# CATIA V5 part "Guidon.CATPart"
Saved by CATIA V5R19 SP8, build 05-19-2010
Part number: Guidon
Nomenclature: 7
Material "Acier": density 7860 kg/m3, Young's modulus 2e+11 Pa, Poisson ratio 0.266, thermal expansion 1.17e-05 1/K
Bounding box of the stored display mesh (mm): x -362.5 to 362.5, y -92.642 to 482.568, z -19.996 to 296.41
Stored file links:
  C:\Users\rphgr\Desktop\0_Tapis_TC520B_vitesse\Guidon.CATPart
  D:\Documents\1_Travail\1 - ac-limoges.fr\ac-limoges.fr\Emmanuel Maynard - STI2D_Turgot\3 - Supports\Tapis de course TC520B\Tapis de course TC520B_Ca\0_Tapis_TC520B.CATProduct
  D:\Documents\1_Travail\1 - ac-limoges.fr\ac-limoges.fr\Emmanuel Maynard - STI2D_Turgot\3 - Supports\Tapis de course TC520B\Tapis de course TC520B_Ca\Montant_Gauche.CATPart
  D:\Programmes\DassaultSysteme\win_b64\startup\materials\French\Catalog.CATMaterial
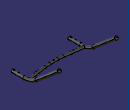
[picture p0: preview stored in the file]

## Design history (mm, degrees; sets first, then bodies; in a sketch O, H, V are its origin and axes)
Set1
  DatumPoint1
  DatumCurve1 to DatumCurve3
Body1 (main body)
  AxisSystem1: origin (0, 0, 0), X (1, 0, 0), Y (0, 1, 0), Z (0, 0, 1)
  Plane1: type OffsetPt, RefPlane YZ plane of AxisSystem1, RefPoint DatumPoint1
  Sketch1 on Plane1, origin (342.5, 0, 0), H (0, 1, 0), V (0, 0, 1)
    point P1 (-92.6422, 0)
    line L1 (-92.6422, 0) -> (47.3578, 0)
    arc A1 centre (47.3578, 240) radius 240 from (47.3578, 0) to (201.6268, 56.1493) ccw
    line L2 (201.6268, 56.1493) -> (469.7424, 281.125)
    reference projected line E1 through (-18.6422, 0) direction (0, -1) from edge of DatumCurve1
    distance E1 P1 = 74
    radius A1 = 240
    length L2 = 350
    angle L2 L1 = 140
    length L1 = 140
    coincidence: P1 H
    horizontal: L1 H
    tangency: A1 L1, L2 A1
  Plane2: type Normal, Curve Sketch1, RefPoint Sketch1.P1
  Plane3: type Angle, RefPlane XY plane of AxisSystem1, Direction edge [XY plane of AxisSystem1 | ZX plane of AxisSystem1], Angle 3
  Sketch2 on Plane2, origin (0, -92.6422, 0), H (-1, 0, 0), V (0, 0, 1)
    circle A1 centre (-342.5, 0) radius 20
    point P1 (-342.5, 0)
    reference projected point E1 (-342.5, 0) from Sketch1.L1
    circle A2 centre (-342.5, 0) radius 19
    radius A1 = 20
    distance A2 A1 = 1
    coincidence: P1 H, P1 E1
  Rib1: profile Sketch2, centre curve Sketch1
  Sketch3 on YZ plane of AxisSystem1, origin (0, 0, 0), H (0, 1, 0), V (0, 0, 1)
    circle A1 centre (57.1522, 2.9952) radius 16
    point P1 (57.1522, 2.9952)
    circle A2 centre (57.1522, 2.9952) radius 15
    reference projected point E1 (57.1522, 2.9952) from Sketch4.L1
    distance A2 A1 = 1
    radius A1 = 16
    coincidence: P1 E1
  Sketch4 on Plane3, origin (0, 0, 0), H (1, 0, 0), V (0, 0.9986, 0.0523)
    line L1 (0, 57.2307) -> (50, 57.2307)
    point P1 (0, 57.2307)
    line L2 (110.3332, 61.807) -> (342.5, 97.2307)
    point P2 (342.5, 97.2307)
    reference intersected line E1 through (0, -92.7693) direction (-1, 0) from face of Rib1
    arc A1 centre (50, 457.2307) radius 400 from (110.3332, 61.807) to (50, 57.2307) cw
    reference projected line E2 (342.5, 47.3578) -> (342.5, 201.6268) from Sketch1.A1
    distance P2 E1 = 190
    distance L1 P2 = 40
    radius A1 = 400
    length L1 = 50
    coincidence: P1 V, P2 E2
    horizontal: L1 H
    tangency: A1 L2, A1 L1
  Rib2: profile Sketch3, centre curve Sketch4
  Sketch5 on ZX plane of AxisSystem1, origin (0, 0, 0), H (0, 0, 1), V (1, 0, 0)
    construction line L1 (0, 71) -> (0, 50)
    point P1 (0, 71)
    point P2 (0, 50)
    line L2 (7.5, 71) -> (7.5, 50)
    line L3 (-7.5, 50) -> (-7.5, 71)
    arc A1 centre (0, 50) radius 7.5 from (7.5, 50) to (-7.5, 50) cw
    arc A2 centre (0, 71) radius 7.5 from (-7.5, 71) to (7.5, 71) cw
    reference intersected line E1 through (0, 0) direction (-1, 0) from YZ plane of AxisSystem1
    distance L1 L2 = 7.5
    length L1 = 21
    distance P2 E1 = 50
    coincidence: P1 V
    vertical: L1 V
    tangency: A1 L2, A2 L2, A1 L3, A2 L3
  Pocket1: profile Sketch5, direction (0, -1, 0), up to face of Rib2
  Sketch6 on XY plane of AxisSystem1, origin (0, 0, 0), H (1, 0, 0), V (0, 1, 0)
    circle A1 centre (0, 57.1522) radius 7.5
    point P1 (0, 57.1522)
    reference projected line E1 through (0, 57.1522) direction (1, 0) from axis of face of Rib2
    radius A1 = 7.5
    coincidence: P1 V, E1 P1
  Pocket2: profile Sketch6, direction (0, 0, 1), through (limit type 3)
  Line1: type PtDir, RefPoint {point type Center, Curve edge [face of Rib1 | face of Rib1]}, Direction face of Rib1, Start 0, End 20
  Point1: type Center, Curve edge [face of Rib2 | face of Rib2]
  Plane4: type 2Lines, Element1 {line type PtDir, RefPoint {point type Center, Curve edge [face of Rib2 | face of Rib2]}, Direction face of Rib2, Start 0, End 20}, Element2 Line1
  Sketch7 on Plane4, origin (-184.1754, 6.5265, -7.7779), H (-0.9891, -0.1469, -0.0047), V (-0.1151, 0.7541, 0.6466)
    construction line L1 (-419.3224, 15.4519) -> (-409.3225, 15.4024)
    point P1 (-419.3224, 15.4519)
    line L2 (-419.2927, 21.4518) -> (-409.2928, 21.4023)
    line L3 (-409.3522, 9.4024) -> (-419.3521, 9.4519)
    arc A1 centre (-409.3225, 15.4024) radius 6 from (-409.2928, 21.4023) to (-409.3522, 9.4024) cw
    arc A2 centre (-419.3224, 15.4519) radius 6 from (-419.3521, 9.4519) to (-419.2927, 21.4518) cw
    reference projected line E1 through (-179.4352, 14.2643) direction (-1, 0.005) from axis of face of Rib2
    reference intersected line E2 through (-534.4003, 0.0001) direction (-0.005, -1) from face of Rib2
    distance L1 L2 = 6
    length L1 = 10
    distance P1 E2 = 115
    tangency: A1 L2, A2 L2, A1 L3, A2 L3
    coincidence: L1 E1
  Pocket3: profile Sketch7, direction (0.0914, -0.6401, 0.7628), through (limit type 3)
  Sketch8 on Plane4, origin (-2.6366, 17.2415, -20.5476), H (0.9891, 0.1469, 0.0047), V (-0.1151, 0.7541, 0.6466)
    circle A1 centre (201.2414, 36.3328) radius 4
    point P1 (201.2414, 36.3328)
    circle A2 centre (265.2406, 36.6496) radius 4
    point P2 (265.2406, 36.6496)
    reference projected point E1 (228.241, 36.4665) from axis of face of Pocket3 from Sketch7.A1
    reference projected line E2 through (-0.0033, 35.3366) direction (1, 0.005) from axis of face of Rib2
    reference projected line E3 through (-0.0033, 35.3366) direction (1, 0.005) from axis of face of Rib2
    reference projected point E4 (238.2409, 36.516) from axis of face of Pocket3 from Sketch7.A2
    radius A2 = 4
    radius A1 = 4
    distance P1 E1 = 27
    distance P2 E4 = 27 {= Sketch8.distance(P1 E1)}
    coincidence: P1 E2, P2 E3
  Pocket4: profile Sketch8, direction (-0.0914, 0.6401, -0.7628), through (limit type 3), opposite side through (limit type 3)
  Sketch9 on XY plane of AxisSystem1, origin (0, 0, 0), H (1, 0, 0), V (0, 1, 0)
    circle A1 centre (342.5, -18.6422) radius 4.85
    point P1 (342.5, -18.6422)
    circle A2 centre (342.5, 41.3578) radius 4.85
    point P2 (342.5, 41.3578)
    reference projected line E1 through (342.5, 0) direction (0, 1) from axis of face of Rib1
    reference projected line E2 through (342.5, 0) direction (0, 1) from axis of face of Rib1
    reference projected point E3 (342.5, -18.6422) from edge of DatumCurve2
    reference projected point E4 (342.5, 41.3578) from edge of DatumCurve3
    radius A2 = 4.85
    radius A1 = 4.85
    coincidence: P2 E1, P1 E2, P1 E3, P2 E4
  Pocket5: profile Sketch9, direction (0, 0, -1), through (limit type 3), opposite side through (limit type 3)
  Sketch10 on XY plane of AxisSystem1, origin (0, 0, 0), H (1, 0, 0), V (0, 1, 0)
    circle A1 centre (342.5, -72.1422) radius 7.5
    point P1 (342.5, -72.1422)
    point P2 (342.5, -92.6422)
    line L1 (345.15, -86.6422) -> (345.15, -98.6422)
    line L2 (345.15, -98.6422) -> (339.85, -98.6422)
    line L3 (339.85, -98.6422) -> (339.85, -86.6422)
    line L4 (339.85, -86.6422) -> (345.15, -86.6422)
    reference projected line E1 through (342.5, 0) direction (0, 1) from axis of face of Rib1
    reference projected line E2 through (342.5, 0) direction (0, 1) from axis of face of Rib1
    reference intersected line E3 through (0, -92.6422) direction (-1, 0) from face of Rib1
    reference intersected line E4 through (0, -92.6422) direction (-1, 0) from face of Rib1
    distance L4 E4 = 6
    distance L1 L3 = 5.3
    radius A1 = 7.5
    distance P1 L4 = 14.5
    vertical: L1 V, L3 V
    horizontal: L2 H, L4 H
    equidistance: L1 L3 P2, L2 L4 P2
    coincidence: P1 E1, P2 E2, P2 E3
  Pocket6: profile Sketch10, direction (0, 0, 1), through (limit type 3)
  Sketch11 on XY plane of AxisSystem1, origin (0, 0, 0), H (1, 0, 0), V (0, 1, 0)
    construction line L1 (342.5, -70.7422) -> (342.5, -73.5422)
    point P1 (342.5, -70.7422)
    point P2 (342.5, -73.5422)
    line L2 (345.5, -70.7422) -> (345.5, -73.5422)
    line L3 (339.5, -73.5422) -> (339.5, -70.7422)
    arc A1 centre (342.5, -73.5422) radius 3 from (345.5, -73.5422) to (339.5, -73.5422) cw
    arc A2 centre (342.5, -70.7422) radius 3 from (339.5, -70.7422) to (345.5, -70.7422) cw
    reference projected line E1 through (342.5, 0) direction (0, 1) from axis of face of Rib1
    reference projected point E2 (342.5, -72.1422) from axis of face of Pocket6 from Sketch10.A1
    distance L1 L2 = 3
    length L1 = 2.8
    vertical: L1 V
    tangency: A1 L2, A2 L2, A1 L3, A2 L3
    coincidence: L1 E1
    equidistance: P1 P2 E2
  Pocket7: profile Sketch11, direction (0, 0, -1), through (limit type 3)
  Mirror1: of the body so far, about YZ plane of AxisSystem1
